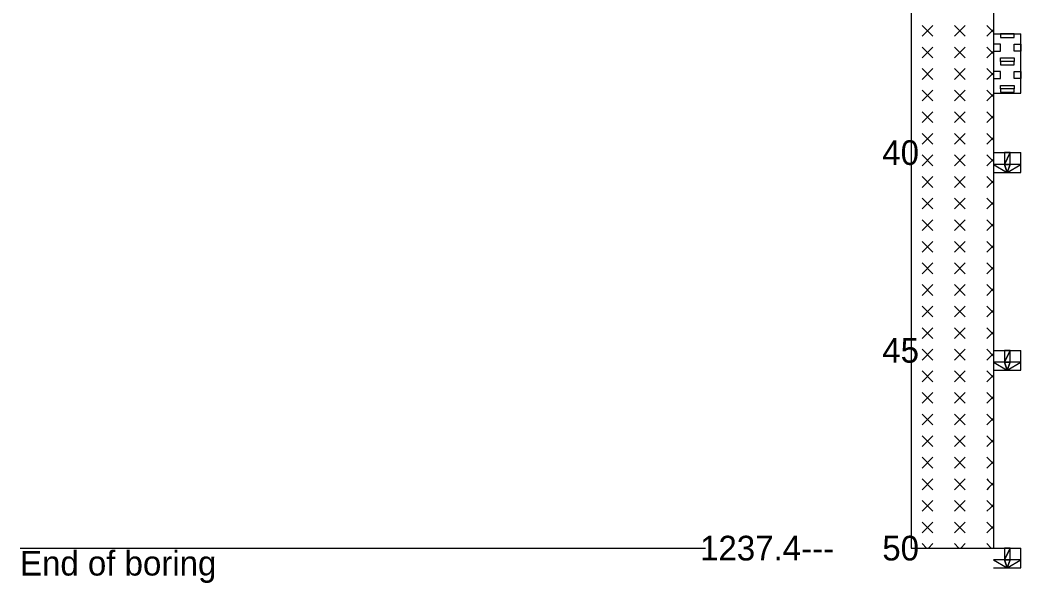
# Model space of a CAD drawing. Extents: x 2150148.6 to 2150220.1, y 143803.7 to 143875.1.
# Drawn here: x 2150197.07 to 2150203.15, y 143846.23 to 143849.65 of the extents above; entities that cross this region are included whole.
import ezdxf

# ---------------------------------------------------------------- set-up
doc = ezdxf.new("R2010")
doc.units = 0
doc.layers.add('Default', color=7, linetype='Continuous')

msp = doc.modelspace()

# ---------------------------------------------------------------- linework, layer by layer
at = {"layer": 'Default'}
for points in [[(2150202.4866, 143858.3678), (2150202.4866, 143846.4416)], [(2150202.9866, 143858.3606), (2150202.9866, 143846.4416)], [(2150202.6178, 143849.6183), (2150202.5522, 143849.5527)], [(2150202.5522, 143849.6183), (2150202.6178, 143849.5527)], [(2150202.8147, 143849.6183), (2150202.749, 143849.5527)], [(2150202.749, 143849.6183), (2150202.8147, 143849.5527)], [(2150202.9459, 143849.6183), (2150202.9866, 143849.5777)], [(2150202.9866, 143849.5934), (2150202.9459, 143849.5527)], [(2150202.9866, 143849.5666), (2150203.1532, 143849.5666)], [(2150203.1532, 143849.206), (2150203.1532, 143849.5666)], [(2150202.6178, 143849.4871), (2150202.5522, 143849.4215)], [(2150202.5522, 143849.4871), (2150202.6178, 143849.4215)], [(2150202.8147, 143849.4871), (2150202.749, 143849.4215)], [(2150202.749, 143849.4871), (2150202.8147, 143849.4215)], [(2150202.9459, 143849.4871), (2150202.9866, 143849.4464)], [(2150202.9866, 143849.4622), (2150202.9459, 143849.4215)], [(2150202.6178, 143849.3559), (2150202.5522, 143849.2903)], [(2150202.5522, 143849.3559), (2150202.6178, 143849.2903)], [(2150202.8147, 143849.3559), (2150202.749, 143849.2903)], [(2150202.749, 143849.3559), (2150202.8147, 143849.2903)], [(2150202.9459, 143849.3559), (2150202.9866, 143849.3152)], [(2150202.9866, 143849.3309), (2150202.9459, 143849.2903)], [(2150202.6178, 143849.2246), (2150202.5522, 143849.159)], [(2150202.5522, 143849.2246), (2150202.6178, 143849.159)], [(2150202.8147, 143849.2246), (2150202.749, 143849.159)], [(2150202.749, 143849.2246), (2150202.8147, 143849.159)], [(2150202.9459, 143849.2246), (2150202.9866, 143849.184)], [(2150202.9866, 143849.1997), (2150202.9459, 143849.159)], [(2150202.9866, 143849.206), (2150203.1532, 143849.206)], [(2150202.6178, 143849.0934), (2150202.5522, 143849.0278)], [(2150202.5522, 143849.0934), (2150202.6178, 143849.0278)], [(2150202.8147, 143849.0934), (2150202.749, 143849.0278)], [(2150202.749, 143849.0934), (2150202.8147, 143849.0278)], [(2150202.9459, 143849.0934), (2150202.9866, 143849.0527)], [(2150202.9866, 143849.0685), (2150202.9459, 143849.0278)], [(2150202.6178, 143848.9622), (2150202.5522, 143848.8966)], [(2150202.5522, 143848.9622), (2150202.6178, 143848.8966)], [(2150202.8147, 143848.9622), (2150202.749, 143848.8966)], [(2150202.749, 143848.9622), (2150202.8147, 143848.8966)], [(2150202.9459, 143848.9622), (2150202.9866, 143848.9215)], [(2150202.9866, 143848.9372), (2150202.9459, 143848.8966)], [(2150202.6178, 143848.8309), (2150202.5522, 143848.7653)], [(2150202.5522, 143848.8309), (2150202.6178, 143848.7653)], [(2150202.8147, 143848.8309), (2150202.749, 143848.7653)], [(2150202.749, 143848.8309), (2150202.8147, 143848.7653)], [(2150202.9459, 143848.8309), (2150202.9866, 143848.7903)], [(2150202.9866, 143848.8455), (2150203.1532, 143848.8455)], [(2150203.1532, 143848.7253), (2150203.1532, 143848.8455)], [(2150202.9866, 143848.806), (2150202.9459, 143848.7653)], [(2150202.9866, 143848.7253), (2150203.1532, 143848.7253)], [(2150202.6178, 143848.6997), (2150202.5522, 143848.6341)], [(2150202.5522, 143848.6997), (2150202.6178, 143848.6341)], [(2150202.8147, 143848.6997), (2150202.749, 143848.6341)], [(2150202.749, 143848.6997), (2150202.8147, 143848.6341)], [(2150202.9459, 143848.6997), (2150202.9866, 143848.659)], [(2150202.9866, 143848.6748), (2150202.9459, 143848.6341)], [(2150202.6178, 143848.5685), (2150202.5522, 143848.5029)], [(2150202.5522, 143848.5685), (2150202.6178, 143848.5029)], [(2150202.8147, 143848.5685), (2150202.749, 143848.5029)], [(2150202.749, 143848.5685), (2150202.8147, 143848.5029)], [(2150202.9459, 143848.5685), (2150202.9866, 143848.5278)], [(2150202.9866, 143848.5435), (2150202.9459, 143848.5029)], [(2150202.6178, 143848.4372), (2150202.5522, 143848.3716)], [(2150202.5522, 143848.4372), (2150202.6178, 143848.3716)], [(2150202.8147, 143848.4372), (2150202.749, 143848.3716)], [(2150202.749, 143848.4372), (2150202.8147, 143848.3716)], [(2150202.9459, 143848.4372), (2150202.9866, 143848.3966)], [(2150202.9866, 143848.4123), (2150202.9459, 143848.3716)], [(2150202.6178, 143848.306), (2150202.5522, 143848.2404)], [(2150202.5522, 143848.306), (2150202.6178, 143848.2404)], [(2150202.8147, 143848.306), (2150202.749, 143848.2404)], [(2150202.749, 143848.306), (2150202.8147, 143848.2404)], [(2150202.9459, 143848.306), (2150202.9866, 143848.2653)], [(2150202.9866, 143848.2811), (2150202.9459, 143848.2404)], [(2150202.6178, 143848.1748), (2150202.5522, 143848.1092)], [(2150202.5522, 143848.1748), (2150202.6178, 143848.1092)], [(2150202.8147, 143848.1748), (2150202.749, 143848.1092)], [(2150202.749, 143848.1748), (2150202.8147, 143848.1092)], [(2150202.9459, 143848.1748), (2150202.9866, 143848.1341)], [(2150202.9866, 143848.1498), (2150202.9459, 143848.1092)], [(2150202.6178, 143848.0435), (2150202.5522, 143847.9779)], [(2150202.5522, 143848.0435), (2150202.6178, 143847.9779)], [(2150202.8147, 143848.0435), (2150202.749, 143847.9779)], [(2150202.749, 143848.0435), (2150202.8147, 143847.9779)], [(2150202.9459, 143848.0435), (2150202.9866, 143848.0029)], [(2150202.9866, 143848.0186), (2150202.9459, 143847.9779)], [(2150202.6178, 143847.9123), (2150202.5522, 143847.8467)], [(2150202.5522, 143847.9123), (2150202.6178, 143847.8467)], [(2150202.8147, 143847.9123), (2150202.749, 143847.8467)], [(2150202.749, 143847.9123), (2150202.8147, 143847.8467)], [(2150202.9459, 143847.9123), (2150202.9866, 143847.8716)], [(2150202.9866, 143847.8874), (2150202.9459, 143847.8467)], [(2150202.6178, 143847.7811), (2150202.5522, 143847.7155)], [(2150202.5522, 143847.7811), (2150202.6178, 143847.7155)], [(2150202.8147, 143847.7811), (2150202.749, 143847.7155)], [(2150202.749, 143847.7811), (2150202.8147, 143847.7155)], [(2150202.9459, 143847.7811), (2150202.9866, 143847.7404)], [(2150202.9866, 143847.7561), (2150202.9459, 143847.7155)], [(2150202.6178, 143847.6498), (2150202.5522, 143847.5842)], [(2150202.5522, 143847.6498), (2150202.6178, 143847.5842)], [(2150202.8147, 143847.6498), (2150202.749, 143847.5842)], [(2150202.749, 143847.6498), (2150202.8147, 143847.5842)], [(2150202.9459, 143847.6498), (2150202.9866, 143847.6092)], [(2150202.9866, 143847.6249), (2150202.9459, 143847.5842)], [(2150202.9866, 143847.6435), (2150203.1532, 143847.6435)], [(2150203.1532, 143847.5233), (2150203.1532, 143847.6435)], [(2150202.6178, 143847.5186), (2150202.5522, 143847.453)], [(2150202.5522, 143847.5186), (2150202.6178, 143847.453)], [(2150202.8147, 143847.5186), (2150202.749, 143847.453)], [(2150202.749, 143847.5186), (2150202.8147, 143847.453)], [(2150202.9459, 143847.5186), (2150202.9866, 143847.4779)], [(2150202.9866, 143847.4937), (2150202.9459, 143847.453)], [(2150202.9866, 143847.5233), (2150203.1532, 143847.5233)], [(2150202.6178, 143847.3874), (2150202.5522, 143847.3218)], [(2150202.5522, 143847.3874), (2150202.6178, 143847.3218)], [(2150202.8147, 143847.3874), (2150202.749, 143847.3218)], [(2150202.749, 143847.3874), (2150202.8147, 143847.3218)], [(2150202.9459, 143847.3874), (2150202.9866, 143847.3467)], [(2150202.9866, 143847.3624), (2150202.9459, 143847.3218)], [(2150202.6178, 143847.2561), (2150202.5522, 143847.1905)], [(2150202.5522, 143847.2561), (2150202.6178, 143847.1905)], [(2150202.8147, 143847.2561), (2150202.749, 143847.1905)], [(2150202.749, 143847.2561), (2150202.8147, 143847.1905)], [(2150202.9459, 143847.2561), (2150202.9866, 143847.2155)], [(2150202.9866, 143847.2312), (2150202.9459, 143847.1905)], [(2150202.6178, 143847.1249), (2150202.5522, 143847.0593)], [(2150202.5522, 143847.1249), (2150202.6178, 143847.0593)], [(2150202.8147, 143847.1249), (2150202.749, 143847.0593)], [(2150202.749, 143847.1249), (2150202.8147, 143847.0593)], [(2150202.9459, 143847.1249), (2150202.9866, 143847.0842)], [(2150202.9866, 143847.1), (2150202.9459, 143847.0593)], [(2150202.6178, 143846.9937), (2150202.5522, 143846.9281)], [(2150202.5522, 143846.9937), (2150202.6178, 143846.9281)], [(2150202.8147, 143846.9937), (2150202.749, 143846.9281)], [(2150202.749, 143846.9937), (2150202.8147, 143846.9281)], [(2150202.9459, 143846.9937), (2150202.9866, 143846.953)], [(2150202.9866, 143846.9687), (2150202.9489, 143846.931), (2150202.9459, 143846.9281)], [(2150202.6178, 143846.8624), (2150202.5522, 143846.7968)], [(2150202.5522, 143846.8624), (2150202.6178, 143846.7968)], [(2150202.8147, 143846.8624), (2150202.749, 143846.7968)], [(2150202.749, 143846.8624), (2150202.8147, 143846.7968)], [(2150202.9459, 143846.8624), (2150202.9548, 143846.8535), (2150202.9866, 143846.8218)], [(2150202.9866, 143846.8375), (2150202.9583, 143846.8092), (2150202.9459, 143846.7968)], [(2150202.6178, 143846.7312), (2150202.5522, 143846.6656)], [(2150202.5522, 143846.7312), (2150202.6178, 143846.6656)], [(2150202.8147, 143846.7312), (2150202.749, 143846.6656)], [(2150202.749, 143846.7312), (2150202.8147, 143846.6656)], [(2150202.9459, 143846.7312), (2150202.9658, 143846.7113), (2150202.9866, 143846.6905)], [(2150202.9866, 143846.7063), (2150202.9676, 143846.6874), (2150202.9459, 143846.6656)], [(2150202.6178, 143846.6), (2150202.5522, 143846.5344)], [(2150202.5522, 143846.6), (2150202.6178, 143846.5344)], [(2150202.8147, 143846.6), (2150202.749, 143846.5344)], [(2150202.749, 143846.6), (2150202.8147, 143846.5344)], [(2150202.9459, 143846.6), (2150202.9767, 143846.5691), (2150202.9866, 143846.5593)], [(2150202.9866, 143846.575), (2150202.977, 143846.5655), (2150202.9459, 143846.5344)], [(2150202.5522, 143846.4687), (2150202.5793, 143846.4416)], [(2150202.6178, 143846.4687), (2150202.5907, 143846.4416)], [(2150202.749, 143846.4687), (2150202.7762, 143846.4416)], [(2150202.8147, 143846.4687), (2150202.7875, 143846.4416)], [(2150202.9459, 143846.4687), (2150202.973, 143846.4416)], [(2150197.0699, 143846.4416), (2150201.2366, 143846.4416)], [(2150202.4866, 143846.4416), (2150202.9866, 143846.4416)], [(2150202.9866, 143846.4438), (2150202.9864, 143846.4437), (2150202.9844, 143846.4416)], [(2150202.9866, 143846.4416), (2150203.1532, 143846.4416)], [(2150203.1532, 143846.3214), (2150203.1532, 143846.4416)], [(2150202.9866, 143846.3214), (2150203.1532, 143846.3214)]]:
    msp.add_lwpolyline(points, dxfattribs=at)
for points in [[(2150203.0282, 143849.5666), (2150203.0282, 143849.5458), (2150203.1116, 143849.5458), (2150203.1116, 143849.5666)], [(2150202.9866, 143849.4624), (2150203.0282, 143849.4624), (2150203.0282, 143849.5041), (2150202.9866, 143849.5041)], [(2150203.1532, 143849.4624), (2150203.1116, 143849.4624), (2150203.1116, 143849.5041), (2150203.1532, 143849.5041)], [(2150203.0282, 143849.3999), (2150203.0282, 143849.4208), (2150203.1116, 143849.4208), (2150203.1116, 143849.3999)], [(2150203.0282, 143849.3999), (2150203.0282, 143849.3791), (2150203.1116, 143849.3791), (2150203.1116, 143849.3999)], [(2150202.9866, 143849.2958), (2150203.0282, 143849.2958), (2150203.0282, 143849.3374), (2150202.9866, 143849.3374)], [(2150203.1532, 143849.2958), (2150203.1116, 143849.2958), (2150203.1116, 143849.3374), (2150203.1532, 143849.3374)], [(2150203.0282, 143849.2333), (2150203.0282, 143849.2541), (2150203.1116, 143849.2541), (2150203.1116, 143849.2333)], [(2150203.0282, 143849.2333), (2150203.0282, 143849.2124), (2150203.1116, 143849.2124), (2150203.1116, 143849.2333)], [(2150203.0532, 143848.7733), (2150203.0866, 143848.7733), (2150203.0866, 143848.8455), (2150203.0532, 143848.7733)], [(2150203.0532, 143848.7733), (2150203.0866, 143848.8455), (2150203.0532, 143848.8455), (2150203.0532, 143848.7733)], [(2150203.0532, 143848.7733), (2150202.9866, 143848.7733), (2150203.0699, 143848.7253), (2150203.0532, 143848.7733)], [(2150203.0532, 143848.7733), (2150203.0699, 143848.7253), (2150203.0866, 143848.7733), (2150203.0532, 143848.7733)], [(2150203.0699, 143848.7253), (2150203.1532, 143848.7733), (2150203.0866, 143848.7733), (2150203.0699, 143848.7253)], [(2150203.0532, 143847.5714), (2150203.0866, 143847.5714), (2150203.0866, 143847.6435), (2150203.0532, 143847.5714)], [(2150203.0532, 143847.5714), (2150203.0866, 143847.6435), (2150203.0532, 143847.6435), (2150203.0532, 143847.5714)], [(2150203.0532, 143847.5714), (2150202.9866, 143847.5714), (2150203.0699, 143847.5233), (2150203.0532, 143847.5714)], [(2150203.0532, 143847.5714), (2150203.0699, 143847.5233), (2150203.0866, 143847.5714), (2150203.0532, 143847.5714)], [(2150203.0699, 143847.5233), (2150203.1532, 143847.5714), (2150203.0866, 143847.5714), (2150203.0699, 143847.5233)], [(2150203.0532, 143846.3695), (2150203.0866, 143846.3695), (2150203.0866, 143846.4416), (2150203.0532, 143846.3695)], [(2150203.0532, 143846.3695), (2150203.0866, 143846.4416), (2150203.0532, 143846.4416), (2150203.0532, 143846.3695)], [(2150203.0532, 143846.3695), (2150202.9866, 143846.3695), (2150203.0699, 143846.3214), (2150203.0532, 143846.3695)], [(2150203.0532, 143846.3695), (2150203.0699, 143846.3214), (2150203.0866, 143846.3695), (2150203.0532, 143846.3695)], [(2150203.0699, 143846.3214), (2150203.1532, 143846.3695), (2150203.0866, 143846.3695), (2150203.0699, 143846.3214)]]:
    msp.add_lwpolyline(points, close=True, dxfattribs=at)

# ---------------------------------------------------------------- texts
for s, p in [('40', (2150202.3104, 143848.7705)), ('45', (2150202.3104, 143847.5685)), ('1237.4---', (2150201.2032, 143846.3666)), ('50', (2150202.3104, 143846.3666)), ('End of boring', (2150197.0699, 143846.275))]:
    msp.add_text(s, height=0.15, dxfattribs=at).set_placement(p)

doc.saveas('drawing.dxf')
